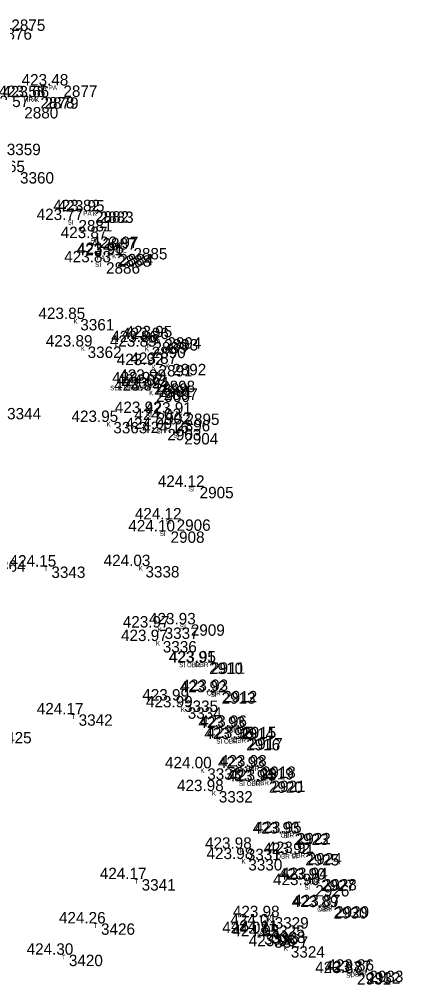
# Model space of a CAD drawing. Extents: x -639390 to -639075, y -1138747 to -1138358.
# Drawn here: x -639264.6 to -639239.4, y -1138459 to -1138395.5 of the extents above; entities that cross this region are included whole.
import ezdxf

# ---------------------------------------------------------------- set-up
doc = ezdxf.new("R2010")
doc.units = 0
for name, color, linetype in [('Vrstva 11', 7, 'Continuous'), ('Vrstva 12', 7, 'Continuous'), ('Vrstva 13', 7, 'Continuous'), ('Vrstva 57', 7, 'Continuous')]:
    doc.layers.add(name, color=color, linetype=linetype)

msp = doc.modelspace()

# ---------------------------------------------------------------- linework, layer by layer
at = {"layer": 'Vrstva 11'}
for p, q in [((-639261.94, -1138399.83), (-639261.94, -1138399.83)), ((-639263.45, -1138400.59), (-639263.45, -1138400.59)), ((-639263.18, -1138400.61), (-639263.18, -1138400.61)), ((-639264.51, -1138401.25), (-639264.51, -1138401.25)), ((-639259.86, -1138408.1), (-639259.86, -1138408.1)), ((-639259.56, -1138408.12), (-639259.56, -1138408.12)), ((-639260.95, -1138408.68), (-639260.95, -1138408.68)), ((-639259.37, -1138409.87), (-639259.37, -1138409.87)), ((-639258.28, -1138410.91), (-639258.28, -1138410.91)), ((-639257.34, -1138410.52), (-639257.34, -1138410.52)), ((-639259.14, -1138411.46), (-639259.14, -1138411.46)), ((-639258.41, -1138411), (-639258.41, -1138411)), ((-639260.83, -1138415.19), (-639260.83, -1138415.19)), ((-639255.32, -1138416.51), (-639255.32, -1138416.51)), ((-639255.11, -1138416.39), (-639255.11, -1138416.39)), ((-639260.35, -1138417), (-639260.35, -1138417)), ((-639256.14, -1138417.01), (-639256.14, -1138417.01)), ((-639256.03, -1138416.71), (-639256.03, -1138416.71)), ((-639255.69, -1138418.22), (-639255.69, -1138418.22)), ((-639254.79, -1138418.14), (-639254.79, -1138418.14)), ((-639255.99, -1138419.42), (-639255.99, -1138419.42)), ((-639255.69, -1138419.58), (-639255.69, -1138419.58)), ((-639255.52, -1138419.25), (-639255.52, -1138419.25)), ((-639255.35, -1138419.76), (-639255.35, -1138419.76)), ((-639255.86, -1138419.9), (-639255.86, -1138419.9)), ((-639255.81, -1138421.37), (-639255.81, -1138421.37)), ((-639253.92, -1138421.41), (-639253.92, -1138421.41)), ((-639258.66, -1138421.96), (-639258.66, -1138421.96)), ((-639254.53, -1138421.83), (-639254.53, -1138421.83)), ((-639255.11, -1138422.42), (-639255.11, -1138422.42)), ((-639254, -1138422.69), (-639254, -1138422.69)), ((-639252.99, -1138426.23), (-639252.99, -1138426.23)), ((-639254.5, -1138428.37), (-639254.5, -1138428.37)), ((-639254.9, -1138429.16), (-639254.9, -1138429.16)), ((-639262.73, -1138431.47), (-639262.73, -1138431.47)), ((-639256.55, -1138431.44), (-639256.55, -1138431.44)), ((-639255.29, -1138435.48), (-639255.29, -1138435.48)), ((-639253.57, -1138435.27), (-639253.57, -1138435.27)), ((-639255.41, -1138436.37), (-639255.41, -1138436.37)), ((-639252.37, -1138437.79), (-639252.37, -1138437.79)), ((-639252.24, -1138437.77), (-639252.24, -1138437.77)), ((-639251.55, -1138439.74), (-639251.55, -1138439.74)), ((-639251.44, -1138439.65), (-639251.44, -1138439.65)), ((-639254.01, -1138440.28), (-639254.01, -1138440.28)), ((-639253.77, -1138440.73), (-639253.77, -1138440.73)), ((-639260.94, -1138441.19), (-639260.94, -1138441.19)), ((-639250.19, -1138442.01), (-639250.19, -1138442.01)), ((-639250.33, -1138442.09), (-639250.33, -1138442.09)), ((-639249.93, -1138442.81), (-639249.93, -1138442.81)), ((-639249.77, -1138442.75), (-639249.77, -1138442.75)), ((-639252.49, -1138444.74), (-639252.49, -1138444.74)), ((-639249.04, -1138444.72), (-639249.04, -1138444.72)), ((-639248.91, -1138444.62), (-639248.91, -1138444.62)), ((-639248.44, -1138445.6), (-639248.44, -1138445.6)), ((-639248.27, -1138445.55), (-639248.27, -1138445.55)), ((-639251.73, -1138446.24), (-639251.73, -1138446.24)), ((-639246.75, -1138449.03), (-639246.75, -1138449.03)), ((-639246.61, -1138448.99), (-639246.61, -1138448.99)), ((-639249.89, -1138450.03), (-639249.89, -1138450.03)), ((-639249.79, -1138450.71), (-639249.79, -1138450.71)), ((-639246.05, -1138450.38), (-639246.05, -1138450.38)), ((-639245.89, -1138450.31), (-639245.89, -1138450.31)), ((-639256.8, -1138452.03), (-639256.8, -1138452.03)), ((-639245.01, -1138452.06), (-639245.01, -1138452.06)), ((-639244.9, -1138452.02), (-639244.9, -1138452.02)), ((-639245.39, -1138452.42), (-639245.39, -1138452.42)), ((-639244.2, -1138453.87), (-639244.2, -1138453.87)), ((-639244.09, -1138453.81), (-639244.09, -1138453.81)), ((-639248.06, -1138454.53), (-639248.06, -1138454.53)), ((-639259.47, -1138454.94), (-639259.47, -1138454.94)), ((-639248.32, -1138455.07), (-639248.32, -1138455.07)), ((-639248.76, -1138455.58), (-639248.76, -1138455.58)), ((-639248.27, -1138455.48), (-639248.27, -1138455.48)), ((-639248.09, -1138455.79), (-639248.09, -1138455.79)), ((-639247, -1138456.44), (-639247, -1138456.44)), ((-639261.58, -1138457), (-639261.58, -1138457)), ((-639242.65, -1138458.21), (-639242.65, -1138458.21)), ((-639242.04, -1138458.15), (-639242.04, -1138458.15)), ((-639241.84, -1138458.05), (-639241.84, -1138458.05))]:
    msp.add_line(p, q, dxfattribs=at)

# ---------------------------------------------------------------- texts
at = {"layer": 'Vrstva 12'}
for s, p in [('423.48 ', (-639264.409, -1138399.83)), ('423.58 ', (-639265.919, -1138400.59)), ('423.66 ', (-639265.666, -1138400.61)), ('423.57 ', (-639266.979, -1138401.25)), ('423.65 ', (-639267.26, -1138405.53)), ('423.82 ', (-639262.329, -1138408.1)), ('423.95 ', (-639262.03, -1138408.12)), ('423.77 ', (-639263.419, -1138408.68)), ('423.87 ', (-639261.839, -1138409.87)), ('423.91 ', (-639260.785, -1138411)), ('423.96 ', (-639260.766, -1138410.91)), ('423.97 ', (-639259.809, -1138410.52)), ('423.83 ', (-639261.609, -1138411.46)), ('423.85 ', (-639263.3, -1138415.19)), ('423.86 ', (-639258.516, -1138416.71)), ('423.96 ', (-639257.806, -1138416.51)), ('423.95 ', (-639257.58, -1138416.39)), ('423.89 ', (-639262.819, -1138417)), ('423.89 ', (-639258.609, -1138417.01)), ('423.92 ', (-639258.159, -1138418.22)), ('423.87 ', (-639257.259, -1138418.14)), ('423.99 ', (-639257.989, -1138419.25)), ('423.97 ', (-639258.459, -1138419.42)), ('423.94 ', (-639258.329, -1138419.9)), ('424.07 ', (-639258.159, -1138419.58)), ('423.94 ', (-639257.819, -1138419.76)), ('423.92 ', (-639258.279, -1138421.37)), ('424.02 ', (-639256.999, -1138421.83)), ('423.91 ', (-639256.295, -1138421.41)), ('423.95 ', (-639261.13, -1138421.96)), ('424.09 ', (-639257.579, -1138422.42)), ('424.16 ', (-639256.486, -1138422.69)), ('424.12 ', (-639255.459, -1138426.23)), ('424.12 ', (-639256.969, -1138428.37)), ('424.10 ', (-639257.399, -1138429.16)), ('424.15 ', (-639265.2, -1138431.47)), ('424.03 ', (-639259.019, -1138431.44)), ('423.97 ', (-639257.759, -1138435.48)), ('423.93 ', (-639256.039, -1138435.27)), ('423.97 ', (-639257.879, -1138436.37)), ('423.91 ', (-639254.745, -1138437.79)), ('423.95 ', (-639254.71, -1138437.77)), ('423.92 ', (-639254.019, -1138439.74)), ('423.93 ', (-639253.909, -1138439.65)), ('423.99 ', (-639256.479, -1138440.28)), ('423.99 ', (-639256.239, -1138440.73)), ('424.17 ', (-639263.409, -1138441.19)), ('423.93 ', (-639252.799, -1138442.09)), ('423.96 ', (-639252.676, -1138442.01)), ('423.92 ', (-639252.399, -1138442.81)), ('423.95 ', (-639252.24, -1138442.75)), ('423.93 ', (-639251.509, -1138444.72)), ('423.98 ', (-639251.379, -1138444.62)), ('424.00 ', (-639254.989, -1138444.74)), ('423.94 ', (-639250.909, -1138445.6)), ('423.95 ', (-639250.74, -1138445.55)), ('423.98 ', (-639254.199, -1138446.24)), ('423.93 ', (-639249.219, -1138449.03)), ('423.95 ', (-639249.08, -1138448.99)), ('423.98 ', (-639252.359, -1138450.03)), ('423.92 ', (-639248.519, -1138450.38)), ('423.91 ', (-639248.265, -1138450.31)), ('423.98 ', (-639252.259, -1138450.71)), ('424.17 ', (-639259.269, -1138452.03)), ('423.90 ', (-639247.509, -1138452.06)), ('423.94 ', (-639247.369, -1138452.02)), ('423.90 ', (-639247.889, -1138452.42)), ('423.89 ', (-639246.669, -1138453.87)), ('423.87 ', (-639246.559, -1138453.81)), ('423.98 ', (-639250.529, -1138454.53)), ('424.26 ', (-639261.956, -1138454.94)), ('424.01 ', (-639250.695, -1138455.07)), ('424.11 ', (-639250.645, -1138455.48)), ('424.08 ', (-639251.229, -1138455.58)), ('424.05 ', (-639250.56, -1138455.79)), ('423.96 ', (-639249.486, -1138456.44)), ('424.30 ', (-639264.079, -1138457)), ('423.86 ', (-639244.326, -1138458.05)), ('423.87 ', (-639245.119, -1138458.21)), ('423.87 ', (-639244.509, -1138458.15))]:
    msp.add_text(s, height=0.75, dxfattribs=at).set_placement(p)
at = {"layer": 'Vrstva 13'}
for s, p in [(' 2875', (-639265.36, -1138396.24)), (' 2876', (-639266.24, -1138396.82)), (' 2877', (-639261.94, -1138400.58)), (' 2878', (-639263.45, -1138401.34)), (' 2879', (-639263.18, -1138401.36)), (' 2880', (-639264.51, -1138402)), (' 3359', (-639265.66, -1138404.41)), (' 3360', (-639264.79, -1138406.28)), (' 2882', (-639259.86, -1138408.85)), (' 2883', (-639259.56, -1138408.87)), (' 2881', (-639260.95, -1138409.43)), (' 2887', (-639259.37, -1138410.62)), (' 2884', (-639258.28, -1138411.66)), (' 2885', (-639257.34, -1138411.27)), (' 2886', (-639259.14, -1138412.21)), (' 2888', (-639258.41, -1138411.75)), (' 3361', (-639260.83, -1138415.94)), (' 2893', (-639255.32, -1138417.26)), (' 2894', (-639255.11, -1138417.14)), (' 3362', (-639260.35, -1138417.75)), (' 2890', (-639256.14, -1138417.76)), (' 2889', (-639256.03, -1138417.46)), (' 2891', (-639255.69, -1138418.97)), (' 2892', (-639254.79, -1138418.89)), (' 2899', (-639255.99, -1138420.17)), (' 2901', (-639255.69, -1138420.33)), (' 2898', (-639255.52, -1138420)), (' 2897', (-639255.35, -1138420.51)), (' 2900', (-639255.86, -1138420.65)), (' 3344', (-639265.64, -1138421.79)), (' 2902', (-639255.81, -1138422.12)), (' 2895', (-639253.92, -1138422.16)), (' 3363', (-639258.66, -1138422.71)), (' 2896', (-639254.53, -1138422.58)), (' 2903', (-639255.11, -1138423.17)), (' 2904', (-639254, -1138423.44)), (' 2905', (-639252.99, -1138426.98)), (' 2906', (-639254.5, -1138429.12)), (' 2908', (-639254.9, -1138429.91)), (' 3364', (-639266.66, -1138431.81)), (' 3343', (-639262.73, -1138432.22)), (' 3338', (-639256.55, -1138432.19)), (' 3337', (-639255.29, -1138436.23)), (' 2909', (-639253.57, -1138436.02)), (' 3336', (-639255.41, -1138437.12)), (' 2910', (-639252.37, -1138438.54)), (' 2911', (-639252.24, -1138438.52)), (' 2913', (-639251.55, -1138440.49)), (' 2912', (-639251.44, -1138440.4)), (' 3335', (-639254.01, -1138441.03)), (' 3334', (-639253.77, -1138441.48)), (' 3342', (-639260.94, -1138441.94)), (' 2915', (-639250.19, -1138442.76)), (' 3425', (-639266.26, -1138443.1)), (' 2914', (-639250.33, -1138442.84)), (' 2916', (-639249.93, -1138443.56)), (' 2917', (-639249.77, -1138443.5)), (' 3333', (-639252.49, -1138445.49)), (' 2919', (-639249.04, -1138445.47)), (' 2918', (-639248.91, -1138445.37)), (' 2920', (-639248.44, -1138446.35)), (' 2921', (-639248.27, -1138446.3)), (' 3332', (-639251.73, -1138446.99)), (' 2923', (-639246.75, -1138449.78)), (' 2922', (-639246.61, -1138449.74)), (' 3331', (-639249.89, -1138450.78)), (' 2924', (-639245.89, -1138451.06)), (' 3330', (-639249.79, -1138451.46)), (' 2925', (-639246.05, -1138451.13)), (' 3341', (-639256.8, -1138452.78)), (' 2927', (-639245.01, -1138452.81)), (' 2928', (-639244.9, -1138452.77)), (' 2926', (-639245.39, -1138453.17)), (' 2930', (-639244.2, -1138454.62)), (' 2929', (-639244.09, -1138454.56)), (' 3329', (-639248.06, -1138455.28)), (' 3426', (-639259.47, -1138455.69)), (' 3325', (-639248.32, -1138455.82)), (' 3326', (-639248.76, -1138456.33)), (' 3328', (-639248.27, -1138456.23)), (' 3327', (-639248.09, -1138456.54)), (' 3324', (-639247, -1138457.19)), (' 3420', (-639261.58, -1138457.75)), (' 2931', (-639242.65, -1138458.96)), (' 2932', (-639242.04, -1138458.9)), (' 2933', (-639241.84, -1138458.8))]:
    msp.add_text(s, height=0.75, dxfattribs=at).set_placement(p)
at = {"layer": 'Vrstva 57'}
for s, p in [('HR PA', (-639263.34, -1138400.13)), ('HR K', (-639264.255, -1138400.91)), ('PA', (-639263.95, -1138400.89)), ('PA', (-639260.36, -1138408.4)), ('K', (-639259.735, -1138408.42)), ('SI', (-639261.388, -1138408.98)), ('PA', (-639259.87, -1138410.17)), ('K', (-639258.455, -1138411.21)), ('K PL', (-639258.415, -1138410.82)), ('SI', (-639259.578, -1138411.76)), ('PA K', (-639259.485, -1138411.3)), ('K', (-639261.005, -1138415.49)), ('KA PL', (-639256.485, -1138416.69)), ('KA', (-639255.82, -1138416.81)), ('K', (-639260.525, -1138417.3)), ('K', (-639256.315, -1138417.31)), ('K', (-639256.205, -1138417.01)), ('K', (-639255.865, -1138418.52)), ('K', (-639254.965, -1138418.44)), ('SLK KAMERA', (-639258.59, -1138419.88)), ('K', (-639256.165, -1138419.72)), ('K', (-639255.695, -1138419.55)), ('K', (-639255.525, -1138420.06)), ('K', (-639256.035, -1138420.2)), ('SI', (-639256.248, -1138421.67)), ('K', (-639254.095, -1138421.71)), ('K', (-639258.835, -1138422.26)), ('K', (-639254.705, -1138422.13)), ('SI', (-639255.548, -1138422.72)), ('SI', (-639254.438, -1138422.99)), ('SI', (-639253.428, -1138426.53)), ('SI', (-639254.938, -1138428.67)), ('SI', (-639255.338, -1138429.46)), ('T', (-639262.93, -1138431.77)), ('K', (-639256.725, -1138431.74)), ('K', (-639255.465, -1138435.78)), ('SI', (-639254.008, -1138435.57)), ('K', (-639255.585, -1138436.67)), ('SI OBR', (-639254.059, -1138438.09)), ('OBR', (-639253.029, -1138438.07)), ('OBR', (-639252.229, -1138439.95)), ('SI', (-639251.988, -1138440.04)), ('K', (-639254.185, -1138440.58)), ('K', (-639253.945, -1138441.03)), ('T', (-639261.14, -1138441.49)), ('OBR', (-639250.979, -1138442.31)), ('SI', (-639250.768, -1138442.39)), ('SI OBR', (-639251.619, -1138443.11)), ('OBR', (-639250.559, -1138443.05)), ('K', (-639252.665, -1138445.04)), ('OBR SI', (-639250.678, -1138445.02)), ('OBR', (-639249.699, -1138444.92)), ('SI OBR', (-639250.129, -1138445.9)), ('OBR', (-639249.059, -1138445.85)), ('K', (-639251.905, -1138446.54)), ('OBR', (-639247.399, -1138449.29)), ('SI', (-639247.188, -1138449.33)), ('K', (-639250.065, -1138450.33)), ('OBR', (-639246.679, -1138450.61)), ('K', (-639249.965, -1138451.01)), ('OBR SI', (-639247.688, -1138450.68)), ('T', (-639257, -1138452.33)), ('OBR', (-639245.799, -1138452.36)), ('OBR', (-639245.689, -1138452.32)), ('SI', (-639245.828, -1138452.72)), ('OBR', (-639244.989, -1138454.17)), ('OBR', (-639244.879, -1138454.11)), ('K', (-639248.235, -1138454.83)), ('T', (-639259.67, -1138455.24)), ('K', (-639248.495, -1138455.37)), ('K', (-639248.935, -1138455.88)), ('SA', (-639248.77, -1138455.78)), ('K', (-639248.265, -1138456.09)), ('K', (-639247.175, -1138456.74)), ('T', (-639261.78, -1138457.3)), ('SI', (-639243.088, -1138458.51)), ('OBR', (-639242.829, -1138458.45)), ('OBR', (-639242.629, -1138458.35))]:
    msp.add_text(s, height=0.3, dxfattribs=at).set_placement(p)

doc.saveas('drawing.dxf')
